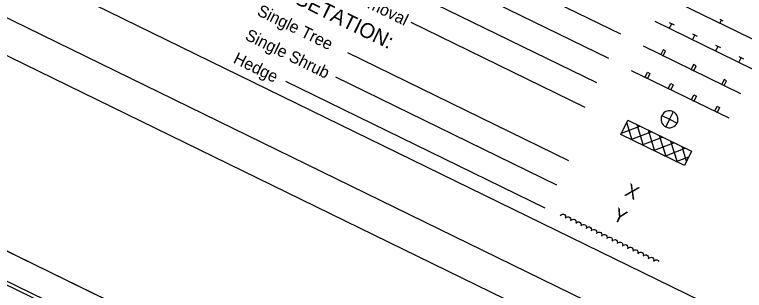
# Model space of a CAD drawing. Extents: x 1517888 to 1526099, y 633375 to 640181.
# Drawn here: x 1522517 to 1523591, y 635585 to 635991 of the extents above; entities that cross this region are included whole.
import ezdxf

# ---------------------------------------------------------------- set-up
doc = ezdxf.new("R2010")
doc.units = 0
for name, color, linetype in [('Default', 7, 'Continuous'), ('Sheet Cutting Line CELL', 7, 'Continuous'), ('Sheet Plan CELL', 7, 'Continuous'), ('Sheet Plot Border Inside CELL', 7, 'Continuous'), ('Sheet Plot Border Outside CELL', 7, 'Continuous')]:
    doc.layers.add(name, color=color, linetype=linetype)

msp = doc.modelspace()

# ---------------------------------------------------------------- linework, layer by layer
at = {"layer": 'Default'}
for p, q in [((1522062.9, 636285.6), (1524954.9, 634871.2)), ((1521963.6, 636251.5), (1524989.1, 634771.8)), ((1523409, 635962.2), (1523221.7, 636053.8)), ((1523373.9, 635890.4), (1523117.8, 636015.7)), ((1523391.5, 635926.3), (1523204.2, 636017.9)), ((1523476.9, 636016.8), (1523620.6, 635946.5)), ((1523356.3, 635854.5), (1523100.2, 635979.7)), ((1523603, 635910.6), (1523459.4, 635980.8)), ((1523480.3, 635979.4), (1523487.5, 635975.9)), ((1523554.8, 635984.2), (1523559.3, 635982)), ((1523554.8, 635978.6), (1523557, 635983.1)), ((1523480.4, 635970.5), (1523483.9, 635977.6)), ((1523514.4, 635962.7), (1523521.6, 635959.2)), ((1523514.5, 635953.9), (1523518, 635960.9)), ((1523548.5, 635946), (1523555.7, 635942.5)), ((1523441.8, 635944.9), (1523585.4, 635874.7)), ((1523548.6, 635937.2), (1523552.1, 635944.3)), ((1523332.5, 635775.9), (1523007.3, 635935)), ((1523582.6, 635929.3), (1523589.8, 635925.8)), ((1523582.8, 635920.5), (1523586.2, 635927.6)), ((1523424.2, 635909), (1523567.9, 635838.8)), ((1523297.6, 635705.7), (1522915.7, 635892.4)), ((1523315, 635740), (1522989.7, 635899.1)), ((1523469.5, 635842.4), (1523480.7, 635836.9)), ((1523486.2, 635848.1), (1523480.7, 635836.9)), ((1523409, 635814.5), (1523419.3, 635835.5)), ((1523425.6, 635806.3), (1523417.7, 635832.2)), ((1523418.8, 635834.4), (1523420.3, 635835)), ((1523419.3, 635835.5), (1523512.9, 635789.7)), ((1523442.3, 635798.2), (1523432.9, 635828.8)), ((1523480.7, 635836.9), (1523475.2, 635825.7)), ((1523480.7, 635836.9), (1523491.9, 635831.4)), ((1523410, 635816.5), (1523437, 635826.8)), ((1523423.7, 635807.3), (1523453.7, 635818.6)), ((1523458.9, 635790), (1523449.6, 635820.7)), ((1523502.6, 635768.7), (1523409, 635814.5)), ((1523440.3, 635799.2), (1523470.4, 635810.5)), ((1523475.6, 635781.9), (1523466.2, 635812.5)), ((1523457, 635791), (1523487, 635802.4)), ((1523492.3, 635773.7), (1523482.8, 635804.4)), ((1523505.9, 635775.4), (1523499.5, 635796.3)), ((1523473.7, 635782.8), (1523503.6, 635794.2)), ((1523512.9, 635789.7), (1523502.6, 635768.7)), ((1523490.3, 635774.7), (1523509, 635781.8)), ((1523319.8, 635694.8), (1523321.2, 635696.2)), ((1523321.2, 635696.2), (1523322.9, 635696.9)), ((1523322.9, 635696.9), (1523324.7, 635697)), ((1523324.7, 635697), (1523326.4, 635696.1)), ((1523326.4, 635696.1), (1523327.4, 635694.5)), ((1523327.4, 635694.5), (1523327.8, 635692.9)), ((1523327.8, 635692.9), (1523327.4, 635691.2)), ((1523327.5, 635691), (1523328.8, 635692.5)), ((1523328.8, 635692.5), (1523330.5, 635693.1)), ((1523330.5, 635693.1), (1523332.3, 635693.2)), ((1523332.3, 635693.2), (1523334, 635692.4)), ((1523334, 635692.4), (1523335, 635690.8)), ((1523335, 635690.8), (1523335.4, 635689.1)), ((1523335.4, 635689.1), (1523335.1, 635687.4)), ((1523335.1, 635687.3), (1523336.5, 635688.7)), ((1523336.5, 635688.7), (1523338.1, 635689.4)), ((1523338.1, 635689.4), (1523340, 635689.5)), ((1523340, 635689.5), (1523341.7, 635688.7)), ((1523341.7, 635688.7), (1523342.7, 635687.1)), ((1523342.7, 635687.1), (1523343.1, 635685.4)), ((1523343.1, 635685.4), (1523342.7, 635683.7)), ((1523342.7, 635683.6), (1523344.1, 635685)), ((1523344.1, 635685), (1523345.8, 635685.7)), ((1523345.8, 635685.7), (1523347.6, 635685.8)), ((1523347.6, 635685.8), (1523349.3, 635684.9)), ((1523349.3, 635684.9), (1523350.3, 635683.3)), ((1523350.3, 635683.3), (1523350.7, 635681.7)), ((1523350.7, 635681.7), (1523350.3, 635680)), ((1523350.4, 635679.8), (1523351.7, 635681.3)), ((1523351.7, 635681.3), (1523353.4, 635681.9)), ((1523353.4, 635681.9), (1523355.2, 635682)), ((1523355.2, 635682), (1523356.9, 635681.2)), ((1523356.9, 635681.2), (1523357.9, 635679.6)), ((1523357.9, 635679.6), (1523358.3, 635677.9)), ((1523358.3, 635677.9), (1523358, 635676.2)), ((1523358, 635676.1), (1523359.4, 635677.6)), ((1523359.4, 635677.6), (1523361, 635678.2)), ((1523361, 635678.2), (1523362.9, 635678.3)), ((1523362.9, 635678.3), (1523364.6, 635677.5)), ((1523364.6, 635677.5), (1523365.6, 635675.9)), ((1523365.6, 635675.9), (1523366, 635674.2)), ((1523366, 635674.2), (1523365.6, 635672.5)), ((1523365.6, 635672.4), (1523367, 635673.8)), ((1523367, 635673.8), (1523368.7, 635674.5)), ((1523368.7, 635674.5), (1523370.5, 635674.6)), ((1523370.5, 635674.6), (1523372.2, 635673.7)), ((1523372.2, 635673.7), (1523373.2, 635672.1)), ((1523373.2, 635672.1), (1523373.6, 635670.5)), ((1523373.6, 635670.5), (1523373.2, 635668.8)), ((1523373.3, 635668.6), (1523374.6, 635670.1)), ((1523374.6, 635670.1), (1523376.3, 635670.7)), ((1523376.3, 635670.7), (1523378.1, 635670.8)), ((1523378.1, 635670.8), (1523379.8, 635670)), ((1523379.8, 635670), (1523380.8, 635668.4)), ((1523380.8, 635668.4), (1523381.2, 635666.7)), ((1523381.2, 635666.7), (1523380.8, 635665)), ((1523382.3, 635666.4), (1523383.9, 635667)), ((1523383.9, 635667), (1523385.7, 635667.1)), ((1523385.7, 635667.1), (1523387.5, 635666.3)), ((1523380.9, 635664.9), (1523382.3, 635666.4)), ((1523387.5, 635666.3), (1523388.4, 635664.7)), ((1523388.4, 635664.7), (1523388.9, 635663)), ((1523388.9, 635663), (1523388.5, 635661.3)), ((1523388.5, 635661.2), (1523389.9, 635662.6)), ((1523389.9, 635662.6), (1523391.5, 635663.3)), ((1523391.5, 635663.3), (1523393.4, 635663.4)), ((1523393.4, 635663.4), (1523395.1, 635662.5)), ((1523395.1, 635662.5), (1523396.1, 635660.9)), ((1523396.1, 635660.9), (1523396.5, 635659.3)), ((1523396.5, 635659.3), (1523396.1, 635657.6)), ((1523396.2, 635657.4), (1523397.5, 635658.9)), ((1523397.5, 635658.9), (1523399.2, 635659.5)), ((1523399.2, 635659.5), (1523401, 635659.6)), ((1523401, 635659.6), (1523402.7, 635658.8)), ((1523402.7, 635658.8), (1523403.7, 635657.2)), ((1523403.7, 635657.2), (1523404.1, 635655.5)), ((1523406.8, 635655.8), (1523408.6, 635655.9)), ((1523408.6, 635655.9), (1523410.3, 635655.1)), ((1523404.1, 635655.5), (1523403.7, 635653.8)), ((1523403.8, 635653.7), (1523405.2, 635655.2)), ((1523405.2, 635655.2), (1523406.8, 635655.8)), ((1523410.3, 635655.1), (1523411.3, 635653.5)), ((1523411.3, 635653.5), (1523411.8, 635651.8)), ((1523411.8, 635651.8), (1523411.4, 635650.1)), ((1523411.4, 635650), (1523412.8, 635651.4)), ((1523412.8, 635651.4), (1523414.4, 635652.1)), ((1523414.4, 635652.1), (1523416.3, 635652.2)), ((1523416.3, 635652.2), (1523418, 635651.3)), ((1523418, 635651.3), (1523419, 635649.7)), ((1523419, 635649.7), (1523419.4, 635648.1)), ((1523419.4, 635648.1), (1523419, 635646.4)), ((1523419, 635646.2), (1523420.4, 635647.7)), ((1523420.4, 635647.7), (1523422.1, 635648.3)), ((1523422.1, 635648.3), (1523423.9, 635648.4)), ((1523423.9, 635648.4), (1523425.6, 635647.6)), ((1523425.6, 635647.6), (1523426.6, 635646)), ((1523426.6, 635646), (1523427, 635644.4)), ((1523427, 635644.4), (1523426.6, 635642.7)), ((1523426.7, 635642.5), (1523428.1, 635644)), ((1523428.1, 635644), (1523429.7, 635644.6)), ((1523429.7, 635644.6), (1523431.5, 635644.7)), ((1523431.5, 635644.7), (1523433.2, 635643.9)), ((1523433.2, 635643.9), (1523434.2, 635642.3)), ((1523434.2, 635642.3), (1523434.7, 635640.6)), ((1523434.7, 635640.6), (1523434.3, 635638.9)), ((1523434.3, 635638.8), (1523435.7, 635640.2)), ((1523435.7, 635640.2), (1523437.3, 635640.9)), ((1523437.3, 635640.9), (1523439.2, 635641)), ((1523439.2, 635641), (1523440.9, 635640.1)), ((1523440.9, 635640.1), (1523441.9, 635638.5)), ((1523441.9, 635638.5), (1523442.3, 635636.9)), ((1523442.3, 635636.9), (1523441.9, 635635.2)), ((1523441.9, 635635.1), (1523443.3, 635636.5)), ((1523443.3, 635636.5), (1523445, 635637.1)), ((1523445, 635637.1), (1523446.8, 635637.2)), ((1523446.8, 635637.2), (1523448.5, 635636.4)), ((1523448.5, 635636.4), (1523449.5, 635634.8)), ((1523449.5, 635634.8), (1523449.9, 635633.2)), ((1523449.9, 635633.2), (1523449.5, 635631.5)), ((1523449.6, 635631.3), (1523450.9, 635632.8)), ((1523450.9, 635632.8), (1523452.6, 635633.4)), ((1523452.6, 635633.4), (1523454.4, 635633.5)), ((1523454.4, 635633.5), (1523456.1, 635632.7)), ((1523456.1, 635632.7), (1523457.1, 635631.1)), ((1523457.1, 635631.1), (1523457.5, 635629.4)), ((1523457.5, 635629.4), (1523457.2, 635627.7)), ((1523457.2, 635627.6), (1523458.6, 635629)), ((1523458.6, 635629), (1523460.2, 635629.7)), ((1523460.2, 635629.7), (1523462.1, 635629.8)), ((1523462.1, 635629.8), (1523463.8, 635628.9)), ((1523463.8, 635628.9), (1523464.8, 635627.3)), ((1523464.8, 635627.3), (1523464.8, 635627.2))]:
    msp.add_line(p, q, dxfattribs=at)
for points in [[(1523467.8, 635932.2), (1523471.4, 635930.5), (1523474.9, 635937.6), (1523471.3, 635939.4)], [(1523512.7, 635910.3), (1523516.3, 635908.5), (1523519.8, 635915.7), (1523516.2, 635917.4)], [(1523448.3, 635906.1), (1523451.9, 635904.4), (1523448.4, 635897.2), (1523444.8, 635898.9)], [(1523557.6, 635888.3), (1523561.2, 635886.5), (1523564.7, 635893.7), (1523561.1, 635895.5)], [(1523482.4, 635889.4), (1523486, 635887.7), (1523482.5, 635880.5), (1523478.9, 635882.3)], [(1523516.6, 635872.8), (1523520.2, 635871), (1523516.6, 635863.8), (1523513, 635865.6)], [(1523550.7, 635856.1), (1523554.3, 635854.3), (1523550.8, 635847.1), (1523547.2, 635848.9)]]:
    msp.add_lwpolyline(points, close=True, dxfattribs=at)
for start, end in [(63.9321, 153.9366), (153.9321, 243.9366), (333.9321, 63.9366), (243.9321, 333.9366)]:
    msp.add_arc((1523480.7, 635836.9), 12.5, start, end, dxfattribs=at)
at = {"layer": 'Sheet Cutting Line CELL'}
msp.add_line((1523118.1, 635342.8), (1520093.5, 636822.1), dxfattribs=at)
at = {"layer": 'Sheet Plan CELL'}
msp.add_lwpolyline([(1523067.8, 635317.3), (1520372.9, 636635.4), (1519450.2, 634748.9), (1522145.2, 633430.8)], close=True, dxfattribs=at)
at = {"layer": 'Sheet Plot Border Inside CELL'}
msp.add_lwpolyline([(1519172.2, 634879.3), (1522165.4, 633415.4), (1523092.5, 635310.8), (1520099.3, 636774.7)], close=True, dxfattribs=at)
at = {"layer": 'Sheet Plot Border Outside CELL'}
for points in [[(1525964.3, 636688.2), (1522938.8, 638168), (1521972.2, 636191.7), (1524997.7, 634712)], [(1519131.3, 634854.8), (1522155.9, 633375.5), (1523118.1, 635342.8), (1520093.5, 636822.1)]]:
    msp.add_lwpolyline(points, close=True, dxfattribs=at)

# ---------------------------------------------------------------- texts
at = {"layer": 'Default'}
for s, height, p in [('Pavement Removal', 17.49, (1522907.5, 636063.9)), ('VEGETATION:', 21.988, (1522890.2, 636026.6)), ('Single Tree', 17.49, (1522872.2, 635991)), ('Single Shrub', 17.49, (1522854.6, 635955.1)), ('Hedge', 17.49, (1522837.2, 635920.7)), ('X', 20, (1523413.3, 635725.3)), ('Y', 20, (1523395.7, 635689.4))]:
    msp.add_text(s, height=height, rotation=333.9377, dxfattribs=at).set_placement(p)

doc.saveas('drawing.dxf')
